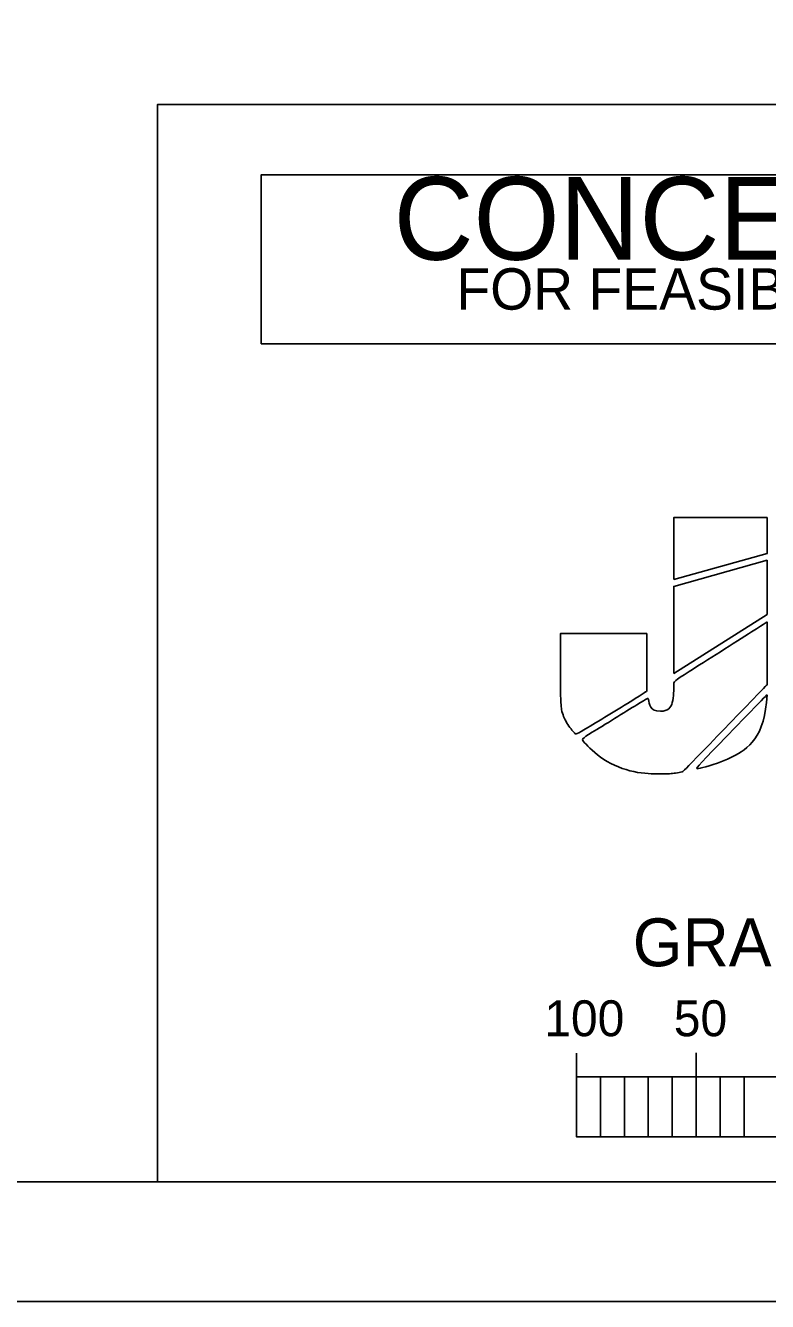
# Model space of a CAD drawing. Extents: x 1637454 to 1644154, y 841334 to 844734.
# Drawn here: x 1642749 to 1643059, y 841334 to 841867 of the extents above; entities that cross this region are included whole.
import ezdxf

# ---------------------------------------------------------------- set-up
doc = ezdxf.new("R2010")
doc.units = 0
for name, color, linetype in [('Default', 7, 'Continuous'), ('Scratch_Level_1', 7, 'Continuous'), ('Sheet Data Field CELL', 7, 'Continuous'), ('Sheet Plan And Profile CELL', 7, 'Continuous'), ('Sheet Sticker Incomplete CELL', 7, 'Continuous'), ('Sheet Title CELL', 7, 'Continuous')]:
    doc.layers.add(name, color=color, linetype=linetype)

msp = doc.modelspace()

# ---------------------------------------------------------------- linework, layer by layer
at = {"layer": 'Default'}
for p, q in [((1643058.8, 841661.36), (1643019.84, 841661.36)), ((1643019.84, 841661.36), (1643019.84, 841635.52)), ((1643058.8, 841661.36), (1643019.84, 841661.36)), ((1643019.84, 841661.36), (1643019.84, 841635.52)), ((1643058.8, 841646.32), (1643058.8, 841661.36)), ((1643058.8, 841646.32), (1643058.8, 841661.36)), ((1643019.84, 841635.52), (1643058.8, 841646.32)), ((1643019.84, 841635.52), (1643058.8, 841646.32)), ((1643058.8, 841643.49), (1643019.84, 841632.56)), ((1643058.8, 841643.49), (1643019.84, 841632.56)), ((1643058.8, 841620.92), (1643058.8, 841643.49)), ((1643058.8, 841620.92), (1643058.8, 841643.49)), ((1643019.84, 841632.56), (1643019.84, 841596.24)), ((1643019.84, 841632.56), (1643019.84, 841596.24)), ((1643019.84, 841596.24), (1643058.8, 841620.92)), ((1643019.84, 841596.24), (1643058.8, 841620.92))]:
    msp.add_line(p, q, dxfattribs=at)
for points in [[(1643019.84, 841635.52), (1643058.8, 841646.32), (1643058.8, 841661.36), (1643019.84, 841661.36), (1643019.84, 841635.52)], [(1643019.84, 841635.52), (1643058.8, 841646.32), (1643058.8, 841661.36), (1643019.84, 841661.36), (1643019.84, 841635.52)], [(1643019.84, 841596.24), (1643058.8, 841620.92), (1643058.8, 841643.49), (1643019.84, 841632.56), (1643019.84, 841596.24)], [(1643019.84, 841596.24), (1643058.8, 841620.92), (1643058.8, 841643.49), (1643019.84, 841632.56), (1643019.84, 841596.24)]]:
    msp.add_lwpolyline(points, dxfattribs=at)
for points in [[(1643014.25, 841580.49), (1643011.94, 841580.49), (1643009.94, 841581.78), (1643009.11, 841586.08), (1643009.11, 841586.08), (1642981.14, 841568.79), (1642981.14, 841568.79), (1642989.76, 841559.73), (1643003.51, 841554.33), (1643015.15, 841554.33), (1643018.17, 841554.33), (1643020.49, 841554.59), (1643023.7, 841555.23), (1643023.7, 841555.23), (1643058.8, 841591.48), (1643058.8, 841591.48), (1643058.8, 841591.48), (1643058.8, 841617.71), (1643058.8, 841617.71), (1643058.8, 841617.71), (1643019.84, 841592.96), (1643019.84, 841592.96), (1643019.84, 841583.13), (1643017.46, 841580.49), (1643014.25, 841580.49)], [(1643014.25, 841580.49), (1643011.94, 841580.49), (1643009.94, 841581.78), (1643009.11, 841586.08), (1643009.11, 841586.08), (1642981.14, 841568.79), (1642981.14, 841568.79), (1642989.76, 841559.73), (1643003.51, 841554.33), (1643015.15, 841554.33), (1643018.17, 841554.33), (1643020.49, 841554.59), (1643023.7, 841555.23), (1643023.7, 841555.23), (1643058.8, 841591.48), (1643058.8, 841591.48), (1643058.8, 841591.48), (1643058.8, 841617.71), (1643058.8, 841617.71), (1643058.8, 841617.71), (1643019.84, 841592.96), (1643019.84, 841592.96), (1643019.84, 841583.13), (1643017.46, 841580.49), (1643014.25, 841580.49)], [(1643014.25, 841580.49), (1643011.94, 841580.49), (1643009.94, 841581.78), (1643009.11, 841586.08), (1643009.11, 841586.08), (1642981.14, 841568.79), (1642981.14, 841568.79), (1642989.76, 841559.73), (1643003.51, 841554.33), (1643015.15, 841554.33), (1643018.17, 841554.33), (1643020.49, 841554.59), (1643023.7, 841555.23), (1643023.7, 841555.23), (1643058.8, 841591.48), (1643058.8, 841591.48), (1643058.8, 841591.48), (1643058.8, 841617.71), (1643058.8, 841617.71), (1643058.8, 841617.71), (1643019.84, 841592.96), (1643019.84, 841592.96), (1643019.84, 841583.13), (1643017.46, 841580.49), (1643014.25, 841580.49)], [(1643014.25, 841580.49), (1643011.94, 841580.49), (1643009.94, 841581.78), (1643009.11, 841586.08), (1643009.11, 841586.08), (1642981.14, 841568.79), (1642981.14, 841568.79), (1642989.76, 841559.73), (1643003.51, 841554.33), (1643015.15, 841554.33), (1643018.17, 841554.33), (1643020.49, 841554.59), (1643023.7, 841555.23), (1643023.7, 841555.23), (1643058.8, 841591.48), (1643058.8, 841591.48), (1643058.8, 841591.48), (1643058.8, 841617.71), (1643058.8, 841617.71), (1643058.8, 841617.71), (1643019.84, 841592.96), (1643019.84, 841592.96), (1643019.84, 841583.13), (1643017.46, 841580.49), (1643014.25, 841580.49)], [(1643008.66, 841612.95), (1643008.66, 841612.95), (1642972.59, 841612.95), (1642972.59, 841612.95), (1642972.59, 841612.95), (1642972.59, 841590.39), (1642972.59, 841590.39), (1642972.59, 841590.39), (1642972.59, 841588.01), (1642972.59, 841588.01), (1642972.6, 841580.94), (1642974.91, 841575.35), (1642979.02, 841570.66), (1642979.02, 841570.66), (1643008.66, 841588.66), (1643008.66, 841589.1), (1643008.66, 841589.1), (1643008.66, 841612.95), (1643008.66, 841612.95)], [(1643008.66, 841612.95), (1643008.66, 841612.95), (1642972.59, 841612.95), (1642972.59, 841612.95), (1642972.59, 841612.95), (1642972.59, 841590.39), (1642972.59, 841590.39), (1642972.59, 841590.39), (1642972.59, 841588.01), (1642972.59, 841588.01), (1642972.6, 841580.94), (1642974.91, 841575.35), (1642979.02, 841570.66), (1642979.02, 841570.66), (1643008.66, 841588.66), (1643008.66, 841589.1), (1643008.66, 841589.1), (1643008.66, 841612.95), (1643008.66, 841612.95)], [(1643008.66, 841612.95), (1643008.66, 841612.95), (1642972.59, 841612.95), (1642972.59, 841612.95), (1642972.59, 841612.95), (1642972.59, 841590.39), (1642972.59, 841590.39), (1642972.59, 841590.39), (1642972.59, 841588.01), (1642972.59, 841588.01), (1642972.6, 841580.94), (1642974.91, 841575.35), (1642979.02, 841570.66), (1642979.02, 841570.66), (1643008.66, 841588.66), (1643008.66, 841589.1), (1643008.66, 841589.1), (1643008.66, 841612.95), (1643008.66, 841612.95)], [(1643008.66, 841612.95), (1643008.66, 841612.95), (1642972.59, 841612.95), (1642972.59, 841612.95), (1642972.59, 841612.95), (1642972.59, 841590.39), (1642972.59, 841590.39), (1642972.59, 841590.39), (1642972.59, 841588.01), (1642972.59, 841588.01), (1642972.6, 841580.94), (1642974.91, 841575.35), (1642979.02, 841570.66), (1642979.02, 841570.66), (1643008.66, 841588.66), (1643008.66, 841589.1), (1643008.66, 841589.1), (1643008.66, 841612.95), (1643008.66, 841612.95)], [(1643058.8, 841587.37), (1643058.8, 841587.37), (1643028.46, 841556.06), (1643028.46, 841556.06), (1643043.3, 841559.73), (1643058.09, 841569.56), (1643058.8, 841587.37)], [(1643058.8, 841587.37), (1643058.8, 841587.37), (1643028.46, 841556.06), (1643028.46, 841556.06), (1643043.3, 841559.73), (1643058.09, 841569.56), (1643058.8, 841587.37)], [(1643058.8, 841587.37), (1643058.8, 841587.37), (1643028.46, 841556.06), (1643028.46, 841556.06), (1643043.3, 841559.73), (1643058.09, 841569.56), (1643058.8, 841587.37)], [(1643058.8, 841587.37), (1643058.8, 841587.37), (1643028.46, 841556.06), (1643028.46, 841556.06), (1643043.3, 841559.73), (1643058.09, 841569.56), (1643058.8, 841587.37)]]:
    msp.add_open_spline(points, degree=3, dxfattribs=at)
at = {"layer": 'Scratch_Level_1'}
msp.add_lwpolyline([(1637454.2, 841333.94), (1637454.2, 844733.94), (1644154.2, 844733.94), (1644154.2, 841333.94)], close=True, dxfattribs=at)
at = {"layer": 'Sheet Plan And Profile CELL'}
msp.add_lwpolyline([(1637504.2, 841383.94), (1637504.2, 844683.94), (1644104.2, 844683.94), (1644104.2, 841383.94)], close=True, dxfattribs=at)
msp.add_lwpolyline([(1643454.2, 841383.94), (1643454.2, 841833.94), (1642804.2, 841833.94), (1642804.2, 841383.94)], dxfattribs=at)
at = {"layer": 'Sheet Sticker Incomplete CELL'}
msp.add_lwpolyline([(1642847.4, 841733.94), (1642847.4, 841804.44), (1643411, 841804.44), (1643411, 841733.94)], close=True, dxfattribs=at)
at = {"layer": 'Sheet Title CELL'}
for p, q in [((1642979.2, 841427.72), (1642979.2, 841437.69)), ((1642979.2, 841437.69), (1642979.2, 841437.69)), ((1643029.2, 841427.69), (1643029.2, 841437.72)), ((1642979.2, 841427.72), (1642979.2, 841402.72)), ((1642979.2, 841427.72), (1642979.2, 841427.72)), ((1643279.2, 841427.72), (1642979.2, 841427.72)), ((1642979.2, 841402.72), (1643279.2, 841402.72))]:
    msp.add_line(p, q, dxfattribs=at)
for points in [[(1642979.2, 841427.72), (1642989.2, 841427.72), (1642989.2, 841402.72), (1642979.2, 841402.72)], [(1642999.2, 841427.72), (1643009.2, 841427.72), (1643009.2, 841402.72), (1642999.2, 841402.72)], [(1643019.2, 841427.72), (1643029.2, 841427.72), (1643029.2, 841402.72), (1643019.2, 841402.72)], [(1643039.2, 841427.72), (1643049.2, 841427.72), (1643049.2, 841402.72), (1643039.2, 841402.72)]]:
    msp.add_lwpolyline(points, close=True, dxfattribs=at)

# ---------------------------------------------------------------- texts
at = {"layer": 'Sheet Data Field CELL'}
for s, p in [('100', (1642965.73, 841444.72)), ('50', (1643019.86, 841444.72))]:
    msp.add_text(s, height=15, dxfattribs=at).set_placement(p)
at = {"layer": 'Sheet Sticker Incomplete CELL'}
for s, height, p in [('CONCEPTUAL DRAWING', 34.56, (1642902.82, 841769.04)), ('FOR FEASIBILITY STUDY PURPOSES ONLY', 17.28, (1642929.03, 841748.19))]:
    msp.add_text(s, height=height, dxfattribs=at).set_placement(p)
at = {"layer": 'Sheet Title CELL'}
msp.add_text('GRAPHIC SCALES', height=19.9992, dxfattribs=at).set_placement((1643002.73, 841473.94))

doc.saveas('drawing.dxf')
